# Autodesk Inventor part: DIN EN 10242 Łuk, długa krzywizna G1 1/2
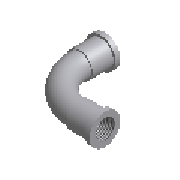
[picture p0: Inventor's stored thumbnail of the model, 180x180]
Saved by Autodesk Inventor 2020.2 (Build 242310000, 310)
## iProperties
Manager: www.cadconsulting.pl
Company: Fabian Stasiak CAD Consulting
Created: 2014-02
Part Number: DIN EN 10242 Łuk, długa krzywizna G1 1/2
Material: Żelazo, ciągliwe
Description: Gięcie
Document SubType Name: Modeling
Standard: DIN EN 10242
Designer: F.Stasiak
Standards Organization: DIN
Language: pl-PL
Size Designation: 1/2
Categories: <MemberInstance><Categories><Category DisplayName="Rury cienko- i grubościenne" InternalName="4347fa0f-2144-441d-94cd-e3e15c92b736" Mnemonic="TUBEANDPIPE"><Cate
Density: 7.15 g/cm^3
Appearance: Częściowo polerowana
Catalog Web Link: www.expertbooks.pl
NAME: PIPING: DIN EN 10242 Long Sweep Bend G1
DATA: <meta><inlinegroups number="0" deflen="0"></inlinegroups><connections number="2"></connections><angles><a>1.57079632679489</a></angles></meta>
IsCustomPart: 0
Author: F.Stasiak
Subject: Zbiór ćwiczeń. Autodesk Inventor 2020. Kurs Professional
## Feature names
1. Revolution1
2. Revolution2
3. Sweep1
## Parameters: a = 55 mm, MD = 18.631 mm, H = 28.21 mm, d0 = 18.631 mm, d1 = 28.21 mm, d2 = 4.34 mm, d3 = 19.5 mm, d26 = 90 deg, d4 = 18.631 mm, d5 = 23.87 mm, d6 = 28.21 mm, d7 = 4.34 mm, d8 = 19.5 mm, d37 = 90 deg, EE = 4.34 mm, D = 21.7 mm, z = 42 mm, d9 = 23.87 mm, d10 = 55 mm, d11 = 0, d16 = 55 mm, d17 = 13 mm, d18 = 13 mm, d19 = 21.7 mm, d91 = 13 mm, d92 = 0, d93 = 13 mm, d94 = 0, d95 = 0, Size_Designation = 5 mm
